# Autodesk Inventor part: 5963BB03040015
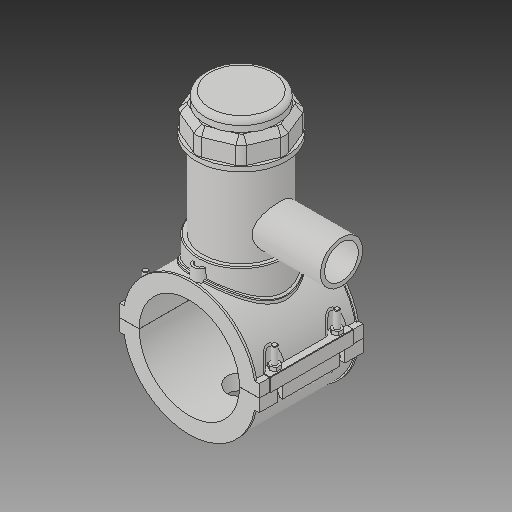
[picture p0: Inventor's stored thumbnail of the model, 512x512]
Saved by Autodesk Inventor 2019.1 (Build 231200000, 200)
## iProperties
Created: 2017-07
Part Number: 5963BB03040015
Material: Generic
Description: PLASSON TAPPING SADDLE 4''IPS x 1 1/2''IPS
Document SubType Name: Modeling
Designer: KIM
Mass: 1712.7 g
Surface Area: 2671.49 cm^2
Volume: 1712.7 cm^3
Density: 1 g/cm^3
Appearance: Default
Author: KIM
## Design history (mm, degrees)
derived "5963B.ipt"
feature "Solid1::5963B.ipt"
feature "Solid2::5963B.ipt"
feature "Solid4::5963B.ipt"
feature "Solid5::5963B.ipt"
tag "TaggingFeature1"
body "Solid1"
body "Solid2"
other parameters: "d0" = 114.1, "d2" = 159.004, "d3" = 28.525, "d4" = 118.11, "d5" = 0, "d6" = 0.1, "d8" = 0, "d19" = 6, "d20" = 6, "d21" = 70.866, "d23" = 0, "d24" = 35.433, "d26" = 0, "d29" = 3, "d30" = 38.03333, "d31" = 6, "d32" = 0, "d33" = 0, "d34" = 0.6, "d40" = 77.1316, "d41" = 102.69, "d43" = 0, "d45" = 0, "d47" = 145.031, "d70" = 15, "d72" = 0, "d73" = 6, "d75" = 5, "d76" = 0, "d77" = 5.705, "d78" = 87.05, "d79" = 15, "d80" = 47.244, "d82" = 5 deg, "d84" = 4, "d85" = 14, "d86" = 0, "d87" = 3, "d88" = 0, "d89" = 1, "d90" = 1, "d91" = 94.488, "d92" = 0, "d93" = 0.5, "d94" = 60.05263, "d96" = 151.2966, "d97" = 2.3622, "d98" = 0, "d102" = 1.141, "d120" = 140 deg, "d121" = 24.228, "d122" = 20 deg, "d123" = 296.66, "d124" = 88.998, "d126" = 0, "d143" = 117.523, "d145" = 26.33077, "d149" = 1.7115, "d150" = 28.96385, "d153" = 118.11, "d154" = 0, "d156" = 74.165, "d157" = 160 deg, "d159" = 6.846, "d161" = 1.7115, "d162" = 70.866, "d163" = 0, "d164" = 57.05, "d167" = 11.41, "d168" = 72.3561, "d170" = 3.2805, "d172" = 0, "d173" = 1, "d175" = 57.05, "d176" = 20 deg, "d177" = 7.987, "d178" = 34.23, "d180" = 0, "d183" = 13.692, "d184" = 6.3896, "d185" = 38.38575, "d186" = 38.38575, "d187" = 74.165, "d188" = 10.269, "d189" = 7.987, "d190" = 0, "d191" = 111.2475, "d193" = 6.1236, "d194" = 4.13385, "d195" = 90 deg, "d197" = 0, "d199" = 0, "d200" = 17.115, "d202" = 0, "d203" = 177.038, "d204" = 97.5555, "d205" = 71.883, "d206" = 87.2865, "d207" = 132.7785, "d208" = 138.08964, "d209" = 164.64534, "d210" = 88.3134, "d211" = 102.69, "d212" = 82.152, "d213" = 36.8766, "d216" = 0, "d217" = 11.41, "d218" = 5.705, "d219" = 1.141, "d222" = 114.1, "d224" = 0, "d230" = 6.846, "d233" = 6, "d236" = 79.502, "d237" = 35.433, "d238" = 6.02433, "d240" = 35.433, "d241" = 35.433, "d242" = 35.433, "d243" = 6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
